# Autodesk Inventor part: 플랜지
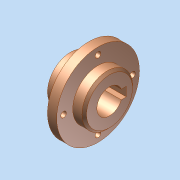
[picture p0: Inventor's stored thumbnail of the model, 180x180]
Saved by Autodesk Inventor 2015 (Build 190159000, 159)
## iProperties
Created: 2026-09
Part Number: 플랜지
Material: 일반
Document SubType Name: Modeling
Designer: SCD-A06
Density: 1 g/cm^3
Appearance: 기본값
Author: SCD-A06
Author: jhkim
Creation Date: 2026-08-27
Sending System: Autodesk Inventor 2027
Preprocessor: ST-DEVELOPER v20.1
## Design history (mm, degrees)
node "플랜지1"
node "솔리드1"
node "기준1"
